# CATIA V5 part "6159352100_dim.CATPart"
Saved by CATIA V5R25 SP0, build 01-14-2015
Part number: 6159352100_dim
Source: made
Property "PROI_CREATED_ON": "12/17/2008 9:21:37 AM"
Property "BLANK_DRAWING": "--"
Property "DRAWN_BY": "FPA"
Property "FINISH": "--"
Property "HEAT_TREATMENT": "ASSIGN"
Property "MATERIAL": "ASSIGN"
Property "PROJECT": "--"
Property "PROTOTYPE_NO": "--"
Property "RELATED_DRAWING": "--"
Property "COMPLETE_MATERIAL": "ASSIGN-ASSIGN"
Property "DESCRIPTION": "Q-SHIELD 30-S"
Property "DRAWING_EXIST": "--"
Property "MANUFACTURER": "--"
Property "MANUFACTURER_2": "--"
Property "MANUFACTURER_REF": "--"
Property "TYPE_PART": "--"
Property "TODAY_DATE": "2021/06/10"
Property "PDMREV": "01.0"
Property "PDMRL": "Production"
Property "PROI_REVISION": "01"
Property "PROI_VERSION": "0"
Property "PROI_RELEASE": "Production"
Property "PTC_MODIFIED": false
Property "MFG_WP_MATERIAL": "ASSIGN"
Property "COMPANY_CODE": "---"
Property "DESCRIPTION_JP": "--"
Property "PQP_DOCUMENT": "--"
Property "GHOST": false
Property "NO_PART": false
Property "PTC_WM_ITERATION": "0"
Property "PTC_WM_VERSION": "01.0"
Property "PTC_WM_CREATED_ON": "10-Jun-21 08:26:52 AM"
Property "PTC_WM_MODIFIED_ON": "10-Jun-21 03:21:17 PM"
Property "PTC_WM_NAME": "6159352100_dim.prt"
Property "PTC_WM_NUMBER": "6159352100_DIM.PRT"
Property "PTC_WM_LIFECYCLE_STATE": "Production"
Property "PTC_WM_LIFECYCLE": "Design_Process"
Property "PTC_WM_REVISION": "01"
Property "PTC_WM_CREATED_BY": "Florian Pavageau (Grefpav) (Grefpav: CPD)"
Property "PTC_WM_MODIFIED_BY": "Florian Pavageau (Grefpav) (Grefpav: CPD)"
Property "PTC_ORGANIZATION_ID": "CPD"
Property "PTC_WM_LOCATION": "/Products/TORQUE MEASUREMENT SYSTEMS/A2010 - DELTAWRENCH GEN2/9-01-Dimensional D"
Property "PTC_WM_PART_NAME": "6159352100_dim.prt"
Property "PTC_WM_PART_NUMBER": "6159352100_DIM"
Property "PTC_WM_TEAM": "Default"
Property "EXPORT_CONTROL": "NULL"
Property "PTC_COMMON_NAME": "6159352100_dim.prt"
Property "PTC_MASTER_MATERIAL": "ASSIGN"
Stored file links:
  d:\ptc\Echange\temp\6159352100_dim.CATPart

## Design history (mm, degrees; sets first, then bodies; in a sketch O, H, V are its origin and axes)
AxisSystem1 "CS0": origin (0, 0, 0), X (1, 0, 0), Y (0, 1, 0), Z (0, 0, 1)
Set1
  DatumSurface1 "Sheet.1"
  DatumSurface2 "Sheet.2"
  DatumSurface3 "Sheet.3"
  DatumSurface4 "Sheet.4"
  DatumSurface5 "Sheet.5"
  DatumSurface6 "Sheet.6"
  DatumSurface7 "Sheet.7"
  DatumSurface8 "Sheet.8"
  DatumSurface9 "Sheet.9"
  Plane1 "RIGHT": stored without definition
  Plane2 "TOP": stored without definition
  Plane3 "FRONT": stored without definition
Body1 "PartBody" (main body)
